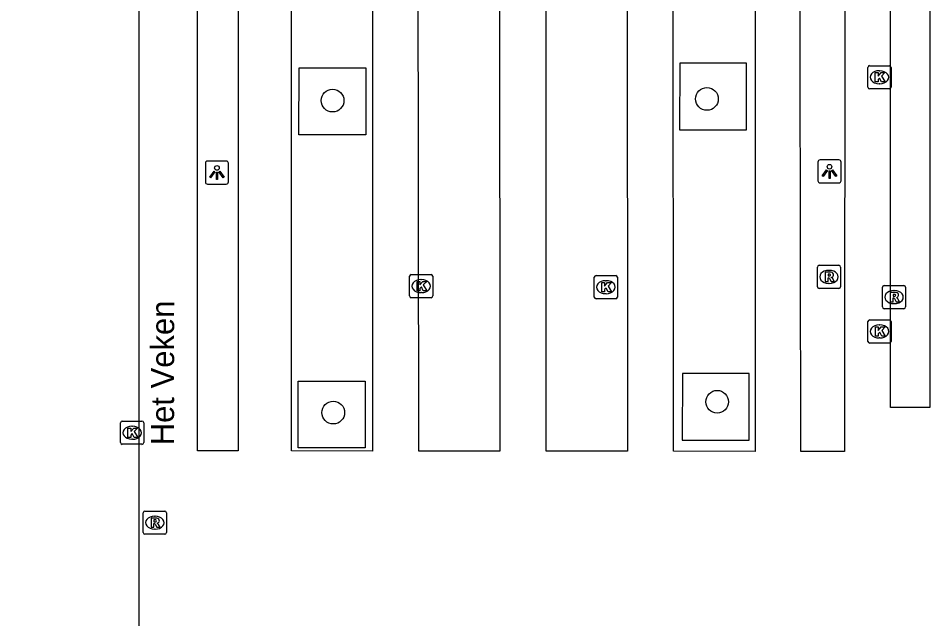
# Model space of a CAD drawing. Extents: x 161477 to 163040, y 383680 to 384868.
# Drawn here: x 162022.66 to 162062.03, y 384298.78 to 384324.69 of the extents above; entities that cross this region are included whole.
import ezdxf

# ---------------------------------------------------------------- set-up
doc = ezdxf.new("R2010")
doc.units = 0
for name, color, linetype in [('IMGEO_Boom', 7, 'Continuous'), ('IMGEO_Kolk', 7, 'Continuous'), ('IMGEO_Lichtpunt', 7, 'Continuous'), ('IMGEO_Openbare_ruimte_label', 7, 'Continuous'), ('IMGEO_Rijbaan_lokaal_open', 7, 'Continuous'), ('IMGEO_Rioolput', 7, 'Continuous'), ('IMGEO_Voetpad_open', 7, 'Continuous')]:
    doc.layers.add(name, color=color, linetype=linetype)

msp = doc.modelspace()

# ---------------------------------------------------------------- linework, layer by layer
at = {"layer": 'IMGEO_Boom'}
for centre in [(162036.236, 384321.136), (162052.408, 384321.207), (162052.847, 384308.141), (162036.266, 384307.672)]:
    msp.add_circle(centre, 0.489, dxfattribs=at)
at = {"layer": 'IMGEO_Kolk'}
for p, q in [((162059.36, 384321.718), (162059.36, 384322.57)), ((162059.435, 384322.644), (162060.287, 384322.644)), ((162060.361, 384322.57), (162060.361, 384321.718)), ((162059.848, 384322.424), (162059.873, 384322.424)), ((162059.871, 384321.864), (162059.846, 384321.864)), ((162060.287, 384321.644), (162059.435, 384321.644)), ((162039.562, 384312.705), (162039.562, 384313.557)), ((162039.637, 384313.631), (162040.489, 384313.631)), ((162040.563, 384313.557), (162040.563, 384312.705)), ((162047.542, 384312.659), (162047.542, 384313.511)), ((162047.617, 384313.585), (162048.469, 384313.585)), ((162048.543, 384313.511), (162048.543, 384312.659)), ((162040.05, 384313.411), (162040.075, 384313.411)), ((162048.03, 384313.365), (162048.055, 384313.365)), ((162040.073, 384312.851), (162040.048, 384312.851)), ((162048.053, 384312.805), (162048.028, 384312.805)), ((162040.489, 384312.631), (162039.637, 384312.631)), ((162048.469, 384312.585), (162047.617, 384312.585)), ((162059.364, 384310.748), (162059.364, 384311.6)), ((162059.439, 384311.674), (162060.291, 384311.674)), ((162060.365, 384311.6), (162060.365, 384310.748)), ((162059.852, 384311.454), (162059.877, 384311.454)), ((162059.875, 384310.894), (162059.85, 384310.894)), ((162060.291, 384310.674), (162059.439, 384310.674)), ((162027.075, 384306.378), (162027.075, 384307.23)), ((162027.15, 384307.304), (162028.002, 384307.304)), ((162028.076, 384307.23), (162028.076, 384306.378)), ((162027.563, 384307.084), (162027.588, 384307.084)), ((162027.586, 384306.524), (162027.561, 384306.524)), ((162028.002, 384306.304), (162027.15, 384306.304))]:
    msp.add_line(p, q, dxfattribs=at)
for points in [[(162059.36, 384321.718), (162059.36, 384322.57)], [(162059.435, 384322.644), (162060.287, 384322.644)], [(162060.361, 384322.57), (162060.361, 384321.718)], [(162059.681, 384322.344), (162059.804, 384322.344), (162059.804, 384322.193), (162059.934, 384322.344), (162060.098, 384322.344), (162059.952, 384322.193), (162060.105, 384321.944), (162059.953, 384321.944), (162059.868, 384322.108), (162059.804, 384322.041), (162059.804, 384321.944), (162059.681, 384321.944), (162059.681, 384322.344)], [(162060.287, 384321.644), (162059.435, 384321.644)], [(162039.562, 384312.705), (162039.562, 384313.557)], [(162039.637, 384313.631), (162040.489, 384313.631)], [(162040.563, 384313.557), (162040.563, 384312.705)], [(162047.542, 384312.659), (162047.542, 384313.511)], [(162047.617, 384313.585), (162048.469, 384313.585)], [(162048.543, 384313.511), (162048.543, 384312.659)], [(162039.883, 384313.331), (162040.006, 384313.331), (162040.006, 384313.18), (162040.136, 384313.331), (162040.3, 384313.331), (162040.154, 384313.18), (162040.307, 384312.931), (162040.155, 384312.931), (162040.07, 384313.095), (162040.006, 384313.028), (162040.006, 384312.931), (162039.883, 384312.931), (162039.883, 384313.331)], [(162047.863, 384313.285), (162047.986, 384313.285), (162047.986, 384313.134), (162048.116, 384313.285), (162048.28, 384313.285), (162048.134, 384313.134), (162048.287, 384312.885), (162048.135, 384312.885), (162048.05, 384313.049), (162047.986, 384312.982), (162047.986, 384312.885), (162047.863, 384312.885), (162047.863, 384313.285)], [(162040.489, 384312.631), (162039.637, 384312.631)], [(162048.469, 384312.585), (162047.617, 384312.585)], [(162059.364, 384310.748), (162059.364, 384311.6)], [(162059.439, 384311.674), (162060.291, 384311.674)], [(162060.365, 384311.6), (162060.365, 384310.748)], [(162059.685, 384311.374), (162059.808, 384311.374), (162059.808, 384311.223), (162059.938, 384311.374), (162060.102, 384311.374), (162059.956, 384311.223), (162060.109, 384310.974), (162059.957, 384310.974), (162059.872, 384311.138), (162059.808, 384311.071), (162059.808, 384310.974), (162059.685, 384310.974), (162059.685, 384311.374)], [(162060.291, 384310.674), (162059.439, 384310.674)], [(162027.075, 384306.378), (162027.075, 384307.23)], [(162027.15, 384307.304), (162028.002, 384307.304)], [(162028.076, 384307.23), (162028.076, 384306.378)], [(162027.396, 384307.004), (162027.519, 384307.004), (162027.519, 384306.853), (162027.649, 384307.004), (162027.813, 384307.004), (162027.667, 384306.853), (162027.82, 384306.604), (162027.668, 384306.604), (162027.583, 384306.768), (162027.519, 384306.701), (162027.519, 384306.604), (162027.396, 384306.604), (162027.396, 384307.004)], [(162028.002, 384306.304), (162027.15, 384306.304)]]:
    msp.add_lwpolyline(points, dxfattribs=at)
for centre, start, end in [((162059.437, 384322.568), 91.552, 178.448), ((162059.437, 384322.568), 91.552, 178.448), ((162060.285, 384322.568), 1.552, 88.448), ((162060.285, 384322.568), 1.552, 88.448), ((162059.437, 384321.72), 181.552, 268.448), ((162059.437, 384321.72), 181.552, 268.448), ((162060.285, 384321.72), 271.552, 358.448), ((162060.285, 384321.72), 271.552, 358.448), ((162039.639, 384313.555), 91.552, 178.448), ((162039.639, 384313.555), 91.552, 178.448), ((162040.487, 384313.555), 1.552, 88.448), ((162040.487, 384313.555), 1.552, 88.448), ((162047.619, 384313.509), 91.552, 178.448), ((162047.619, 384313.509), 91.552, 178.448), ((162048.467, 384313.509), 1.552, 88.448), ((162048.467, 384313.509), 1.552, 88.448), ((162039.639, 384312.707), 181.552, 268.448), ((162039.639, 384312.707), 181.552, 268.448), ((162040.487, 384312.707), 271.552, 358.448), ((162040.487, 384312.707), 271.552, 358.448), ((162047.619, 384312.661), 181.552, 268.448), ((162047.619, 384312.661), 181.552, 268.448), ((162048.467, 384312.661), 271.552, 358.448), ((162048.467, 384312.661), 271.552, 358.448), ((162059.441, 384311.598), 91.552, 178.448), ((162059.441, 384311.598), 91.552, 178.448), ((162060.289, 384311.598), 1.552, 88.448), ((162060.289, 384311.598), 1.552, 88.448), ((162059.441, 384310.75), 181.552, 268.448), ((162059.441, 384310.75), 181.552, 268.448), ((162060.289, 384310.75), 271.552, 358.448), ((162060.289, 384310.75), 271.552, 358.448), ((162027.152, 384307.228), 91.552, 178.448), ((162027.152, 384307.228), 91.552, 178.448), ((162028, 384307.228), 1.552, 88.448), ((162028, 384307.228), 1.552, 88.448), ((162027.152, 384306.38), 181.552, 268.448), ((162027.152, 384306.38), 181.552, 268.448), ((162028, 384306.38), 271.552, 358.448), ((162028, 384306.38), 271.552, 358.448)]:
    msp.add_arc(centre, 0.0765, start, end, dxfattribs=at)
for centre, major_axis, ratio, start_param, end_param in [((162059.847, 384322.144), (-0.387, 0.002), 0.722429, 4.712389, 7.853982), ((162059.872, 384322.144), (-0.39, 0.002), 0.717154, 1.570796, 4.712389), ((162040.049, 384313.131), (-0.387, 0.002), 0.722429, 4.712389, 7.853982), ((162040.074, 384313.131), (-0.39, 0.002), 0.717154, 1.570796, 4.712389), ((162048.029, 384313.085), (-0.387, 0.002), 0.722429, 4.712389, 7.853982), ((162048.054, 384313.085), (-0.39, 0.002), 0.717154, 1.570796, 4.712389), ((162059.851, 384311.174), (-0.387, 0.002), 0.722429, 4.712389, 7.853982), ((162059.876, 384311.174), (-0.39, 0.002), 0.717154, 1.570796, 4.712389), ((162027.562, 384306.804), (-0.387, 0.002), 0.722429, 4.712389, 7.853982), ((162027.587, 384306.804), (-0.39, 0.002), 0.717154, 1.570796, 4.712389)]:
    msp.add_ellipse(centre, major_axis=major_axis, ratio=ratio, start_param=start_param, end_param=end_param, dxfattribs=at)
at = {"layer": 'IMGEO_Lichtpunt'}
for p, q in [((162030.739, 384318.432), (162030.739, 384317.625)), ((162030.739, 384318.432), (162030.739, 384317.625)), ((162031.641, 384318.527), (162030.833, 384318.527)), ((162031.641, 384318.527), (162030.833, 384318.527)), ((162031.735, 384317.625), (162031.735, 384318.432)), ((162031.735, 384317.625), (162031.735, 384318.432)), ((162057.204, 384318.484), (162057.204, 384317.677)), ((162057.204, 384318.484), (162057.204, 384317.677)), ((162058.106, 384318.579), (162057.298, 384318.579)), ((162058.106, 384318.579), (162057.298, 384318.579)), ((162058.2, 384317.677), (162058.2, 384318.484)), ((162058.2, 384317.677), (162058.2, 384318.484)), ((162030.833, 384317.531), (162031.641, 384317.531)), ((162030.833, 384317.531), (162031.641, 384317.531)), ((162057.298, 384317.583), (162058.106, 384317.583)), ((162057.298, 384317.583), (162058.106, 384317.583))]:
    msp.add_line(p, q, dxfattribs=at)
for points in [[(162031.113, 384318.096), (162031.152, 384318.068), (162030.964, 384317.806), (162030.926, 384317.833), (162031.113, 384318.096)], [(162031.215, 384318.048), (162031.262, 384318.048), (162031.262, 384317.726), (162031.215, 384317.726), (162031.215, 384318.048)], [(162031.325, 384318.068), (162031.363, 384318.095), (162031.55, 384317.833), (162031.511, 384317.805), (162031.325, 384318.068)], [(162057.578, 384318.148), (162057.617, 384318.12), (162057.429, 384317.858), (162057.391, 384317.885), (162057.578, 384318.148)], [(162057.68, 384318.1), (162057.727, 384318.1), (162057.727, 384317.778), (162057.68, 384317.778), (162057.68, 384318.1)], [(162057.79, 384318.12), (162057.828, 384318.147), (162058.015, 384317.885), (162057.976, 384317.857), (162057.79, 384318.12)]]:
    msp.add_lwpolyline(points, dxfattribs=at)
for centre in [(162031.238, 384318.23), (162057.703, 384318.282)]:
    msp.add_circle(centre, 0.0994, dxfattribs=at)
for centre, start, end in [((162030.833, 384318.432), 90, 180), ((162030.833, 384318.432), 90, 180), ((162031.641, 384318.432), 0, 90), ((162031.641, 384318.432), 0, 90), ((162057.298, 384318.484), 90, 180), ((162057.298, 384318.484), 90, 180), ((162058.106, 384318.484), 0, 90), ((162058.106, 384318.484), 0, 90), ((162030.833, 384317.625), 180, 270), ((162030.833, 384317.625), 180, 270), ((162031.641, 384317.625), 270, 0), ((162031.641, 384317.625), 270, 360), ((162057.298, 384317.677), 180, 270), ((162057.298, 384317.677), 180, 270), ((162058.106, 384317.677), 270, 0), ((162058.106, 384317.677), 270, 360)]:
    msp.add_arc(centre, 0.0946, start, end, dxfattribs=at)
at = {"layer": 'IMGEO_Rijbaan_lokaal_open'}
msp.add_lwpolyline([(162021.759, 384349.699), (162021.759, 384368.798), (162027.862, 384368.791), (162027.862, 384282.06), (162027.95, 384253.54)], dxfattribs=at)
at = {"layer": 'IMGEO_Rioolput'}
for p, q in [((162057.179, 384313.104), (162057.179, 384313.956)), ((162057.254, 384314.03), (162058.106, 384314.03)), ((162058.18, 384313.956), (162058.18, 384313.104)), ((162057.667, 384313.81), (162057.692, 384313.81)), ((162057.69, 384313.25), (162057.665, 384313.25)), ((162059.989, 384312.231), (162059.989, 384313.083)), ((162060.064, 384313.157), (162060.916, 384313.157)), ((162060.99, 384313.083), (162060.99, 384312.231)), ((162058.106, 384313.03), (162057.254, 384313.03)), ((162060.477, 384312.937), (162060.502, 384312.937)), ((162060.5, 384312.377), (162060.475, 384312.377)), ((162060.916, 384312.157), (162060.064, 384312.157)), ((162028.056, 384302.496), (162028.056, 384303.348)), ((162028.131, 384303.422), (162028.983, 384303.422)), ((162029.057, 384303.348), (162029.057, 384302.496)), ((162028.544, 384303.202), (162028.569, 384303.202)), ((162028.567, 384302.642), (162028.542, 384302.642)), ((162028.983, 384302.422), (162028.131, 384302.422))]:
    msp.add_line(p, q, dxfattribs=at)
for points in [[(162057.179, 384313.104), (162057.179, 384313.956)], [(162057.254, 384314.03), (162058.106, 384314.03)], [(162058.18, 384313.956), (162058.18, 384313.104)], [(162057.768, 384313.728), (162057.516, 384313.73), (162057.516, 384313.33)], [(162057.516, 384313.33), (162057.64, 384313.33), (162057.64, 384313.492), (162057.651, 384313.492)], [(162057.694, 384313.649), (162057.64, 384313.649), (162057.64, 384313.568)], [(162057.64, 384313.568), (162057.692, 384313.568)], [(162057.698, 384313.463), (162057.769, 384313.33), (162057.909, 384313.33), (162057.844, 384313.456)], [(162059.989, 384312.231), (162059.989, 384313.083)], [(162060.064, 384313.157), (162060.916, 384313.157)], [(162060.99, 384313.083), (162060.99, 384312.231)], [(162058.106, 384313.03), (162057.254, 384313.03)], [(162060.578, 384312.855), (162060.326, 384312.857), (162060.326, 384312.457)], [(162060.504, 384312.776), (162060.45, 384312.776), (162060.45, 384312.695)], [(162060.45, 384312.695), (162060.502, 384312.695)], [(162060.326, 384312.457), (162060.45, 384312.457), (162060.45, 384312.619), (162060.461, 384312.619)], [(162060.508, 384312.59), (162060.579, 384312.457), (162060.719, 384312.457), (162060.654, 384312.583)], [(162060.916, 384312.157), (162060.064, 384312.157)], [(162028.056, 384302.496), (162028.056, 384303.348)], [(162028.131, 384303.422), (162028.983, 384303.422)], [(162029.057, 384303.348), (162029.057, 384302.496)], [(162028.645, 384303.12), (162028.393, 384303.122), (162028.393, 384302.722)], [(162028.393, 384302.722), (162028.517, 384302.722), (162028.517, 384302.884), (162028.528, 384302.884)], [(162028.571, 384303.041), (162028.517, 384303.041), (162028.517, 384302.96)], [(162028.517, 384302.96), (162028.569, 384302.96)], [(162028.575, 384302.855), (162028.646, 384302.722), (162028.786, 384302.722), (162028.721, 384302.848)], [(162028.983, 384302.422), (162028.131, 384302.422)]]:
    msp.add_lwpolyline(points, dxfattribs=at)
for centre, radius, start, end in [((162057.256, 384313.954), 0.0765, 91.552, 178.448), ((162057.256, 384313.954), 0.0765, 91.552, 178.448), ((162058.104, 384313.954), 0.0765, 1.552, 88.448), ((162058.104, 384313.954), 0.0765, 1.552, 88.448), ((162057.65, 384313.439), 0.0533, 26.0293, 88.6989), ((162057.676, 384313.757), 0.19, 274.7715, 282.9687), ((162057.7, 384313.553), 0.0964, 77.0061, 93.1865), ((162057.714, 384313.61), 0.0378, 276.6634, 79.6772), ((162057.767, 384313.618), 0.109, 350.3612, 89.416), ((162057.765, 384313.618), 0.112, 277.5842, 350.9817), ((162057.749, 384313.403), 0.108, 29.5134, 73.7905), ((162057.256, 384313.106), 0.0765, 181.552, 268.448), ((162057.256, 384313.106), 0.0765, 181.552, 268.448), ((162058.104, 384313.106), 0.0765, 271.552, 358.448), ((162058.104, 384313.106), 0.0765, 271.552, 358.448), ((162060.066, 384313.081), 0.0765, 91.552, 178.448), ((162060.066, 384313.081), 0.0765, 91.552, 178.448), ((162060.914, 384313.081), 0.0765, 1.552, 88.448), ((162060.914, 384313.081), 0.0765, 1.552, 88.448), ((162060.486, 384312.884), 0.19, 274.7715, 282.9687), ((162060.51, 384312.68), 0.0964, 77.0061, 93.1865), ((162060.524, 384312.737), 0.0378, 276.6634, 79.6772), ((162060.577, 384312.745), 0.109, 350.3612, 89.416), ((162060.575, 384312.745), 0.112, 277.5842, 350.9817), ((162060.46, 384312.566), 0.0533, 26.0293, 88.6989), ((162060.559, 384312.53), 0.108, 29.5134, 73.7905), ((162060.066, 384312.233), 0.0765, 181.552, 268.448), ((162060.066, 384312.233), 0.0765, 181.552, 268.448), ((162060.914, 384312.233), 0.0765, 271.552, 358.448), ((162060.914, 384312.233), 0.0765, 271.552, 358.448), ((162028.133, 384303.346), 0.0765, 91.552, 178.448), ((162028.133, 384303.346), 0.0765, 91.552, 178.448), ((162028.981, 384303.346), 0.0765, 1.552, 88.448), ((162028.981, 384303.346), 0.0765, 1.552, 88.448), ((162028.527, 384302.831), 0.0533, 26.0293, 88.6989), ((162028.553, 384303.149), 0.19, 274.7715, 282.9687), ((162028.577, 384302.945), 0.0964, 77.0061, 93.1865), ((162028.591, 384303.002), 0.0378, 276.6634, 79.6772), ((162028.644, 384303.01), 0.109, 350.3612, 89.416), ((162028.642, 384303.01), 0.112, 277.5842, 350.9817), ((162028.626, 384302.795), 0.108, 29.5134, 73.7905), ((162028.133, 384302.498), 0.0765, 181.552, 268.448), ((162028.133, 384302.498), 0.0765, 181.552, 268.448), ((162028.981, 384302.498), 0.0765, 271.552, 358.448), ((162028.981, 384302.498), 0.0765, 271.552, 358.448)]:
    msp.add_arc(centre, radius, start, end, dxfattribs=at)
for centre, major_axis, ratio, start_param, end_param in [((162057.666, 384313.53), (-0.387, 0.002), 0.722429, 4.712389, 7.853982), ((162057.691, 384313.53), (-0.39, 0.002), 0.717154, 1.570796, 4.712389), ((162060.476, 384312.657), (-0.387, 0.002), 0.722429, 4.712389, 7.853982), ((162060.501, 384312.657), (-0.39, 0.002), 0.717154, 1.570796, 4.712389), ((162028.543, 384302.922), (-0.387, 0.002), 0.722429, 4.712389, 7.853982), ((162028.568, 384302.922), (-0.39, 0.002), 0.717154, 1.570796, 4.712389)]:
    msp.add_ellipse(centre, major_axis=major_axis, ratio=ratio, start_param=start_param, end_param=end_param, dxfattribs=at)
at = {"layer": 'IMGEO_Voetpad_open'}
for points in [[(162037.963, 384306.015), (162034.462, 384306.018), (162034.462, 384311.653), (162034.463, 384335.713), (162034.464, 384349.736), (162037.963, 384349.738), (162037.963, 384306.015)], [(162043.462, 384306.009), (162039.959, 384306.013), (162039.9, 384349.712), (162043.438, 384349.714), (162043.462, 384306.009)], [(162048.971, 384306.004), (162045.463, 384306.007), (162045.457, 384349.742), (162048.946, 384349.714), (162048.971, 384306.004)], [(162054.484, 384305.998), (162050.956, 384306.002), (162050.932, 384349.745), (162054.48, 384349.766), (162054.484, 384305.998)], [(162058.35, 384305.995), (162056.463, 384305.996), (162056.394, 384349.736), (162058.381, 384349.812), (162058.35, 384305.995)], [(162032.16, 384306.021), (162030.395, 384306.022), (162030.395, 384349.644), (162032.16, 384349.644), (162032.16, 384306.021)], [(162060.331, 384345.744), (162062.033, 384345.744), (162062.033, 384307.896), (162060.331, 384307.896), (162060.331, 384345.744)], [(162037.669, 384322.548), (162037.668, 384319.666), (162034.776, 384319.659), (162034.785, 384322.548), (162037.669, 384322.548)], [(162054.114, 384322.759), (162051.229, 384322.759), (162051.22, 384319.87), (162054.112, 384319.877), (162054.114, 384322.759)], [(162054.235, 384309.367), (162051.35, 384309.367), (162051.341, 384306.478), (162054.233, 384306.485), (162054.235, 384309.367)], [(162037.639, 384309.035), (162037.638, 384306.153), (162034.746, 384306.146), (162034.755, 384309.035), (162037.639, 384309.035)]]:
    msp.add_lwpolyline(points, dxfattribs=at)

# ---------------------------------------------------------------- texts
at = {"layer": 'IMGEO_Openbare_ruimte_label'}
msp.add_text('Het Veken', height=1, rotation=89.9427, dxfattribs=at).set_placement((162029.386, 384306.263))

doc.saveas('drawing.dxf')
